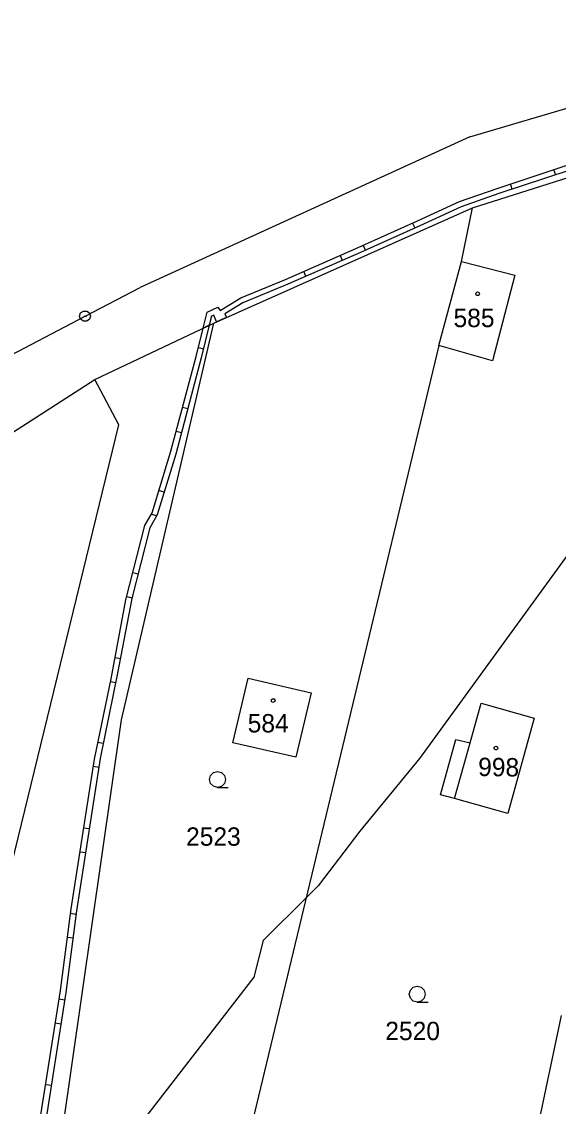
# Model space of a CAD drawing. Extents: x -760611 to -758411, y -1176479 to -1174807.
# Drawn here: x -759409.4 to -759359.7, y -1175181.7 to -1175081.4 of the extents above; entities that cross this region are included whole.
import ezdxf

# ---------------------------------------------------------------- set-up
doc = ezdxf.new("R2010")
doc.units = 0
for name, color, linetype in [('1', 7, 'Continuous'), ('11', 7, 'Continuous'), ('12', 7, 'Continuous'), ('13', 7, 'Continuous'), ('2', 7, 'Continuous'), ('3', 7, 'Continuous'), ('4', 7, 'Continuous'), ('5', 7, 'Continuous'), ('8', 7, 'Continuous')]:
    doc.layers.add(name, color=color, linetype=linetype)

msp = doc.modelspace()

# ---------------------------------------------------------------- linework, layer by layer
at = {"layer": '1'}
for p, q in [((-759367.91, -1175092.06), (-759342.24, -1175084.47)), ((-759367.67, -1175098.62), (-759342.79, -1175090.74)), ((-759367.91, -1175092.06), (-759398.41, -1175106)), ((-759391.61, -1175109.29), (-759367.67, -1175098.62)), ((-759368.7, -1175103.58), (-759367.67, -1175098.62)), ((-759370.78, -1175111.37), (-759368.7, -1175103.58)), ((-759368.7, -1175103.58), (-759363.77, -1175104.85)), ((-759363.77, -1175104.85), (-759365.83, -1175112.77)), ((-759403.51, -1175108.65), (-759398.41, -1175106)), ((-759435.58, -1175125.4), (-759403.51, -1175108.65)), ((-759402.6, -1175114.51), (-759391.61, -1175109.29)), ((-759400.15, -1175145.98), (-759391.61, -1175109.29)), ((-759370.78, -1175111.37), (-759392.87, -1175203.23)), ((-759365.83, -1175112.77), (-759370.78, -1175111.37)), ((-759421.5, -1175126.66), (-759402.6, -1175114.51)), ((-759400.38, -1175118.69), (-759402.6, -1175114.51)), ((-759410.58, -1175160.57), (-759400.38, -1175118.69)), ((-759389.84, -1175148.1), (-759388.44, -1175142.14)), ((-759388.44, -1175142.14), (-759382.61, -1175143.5)), ((-759382.61, -1175143.5), (-759384.01, -1175149.45)), ((-759367.9, -1175148.1), (-759366.88, -1175144.44)), ((-759366.88, -1175144.44), (-759361.98, -1175145.83)), ((-759408.44, -1175203.92), (-759400.15, -1175145.98)), ((-759361.98, -1175145.83), (-759364.42, -1175154.64)), ((-759384.01, -1175149.45), (-759389.84, -1175148.1)), ((-759370.64, -1175152.91), (-759369.21, -1175147.8)), ((-759369.21, -1175147.8), (-759367.9, -1175148.1)), ((-759369.34, -1175153.26), (-759370.64, -1175152.91)), ((-759364.42, -1175154.64), (-759369.34, -1175153.26)), ((-759359.46, -1175173.34), (-759362.4, -1175187.18))]:
    msp.add_line(p, q, dxfattribs=at)
at = {"layer": '11'}
msp.add_lwpolyline([(-759277.4, -1175081.41), (-759285.99, -1175083.38), (-759286.68, -1175083.54), (-759295.93, -1175086.38), (-759305.65, -1175089.38), (-759307.82, -1175090.04), (-759312.08, -1175091.35), (-759315.12, -1175092.29), (-759315.34, -1175092.43), (-759325.61, -1175098.82), (-759334.67, -1175104.46), (-759335.87, -1175105.55), (-759347.99, -1175116.51), (-759349.56, -1175117.93), (-759372.57, -1175149.55), (-759378.11, -1175156.29), (-759381.94, -1175161.35), (-759383.07, -1175162.46), (-759387.05, -1175166.4), (-759387.91, -1175169.78), (-759407.11, -1175194.59)], dxfattribs=at)
at = {"layer": '12'}
for p, q in [((-759370.78, -1175111.37), (-759368.7, -1175103.58)), ((-759368.7, -1175103.58), (-759363.77, -1175104.85)), ((-759363.77, -1175104.85), (-759365.83, -1175112.77)), ((-759365.83, -1175112.77), (-759370.78, -1175111.37)), ((-759389.84, -1175148.1), (-759388.44, -1175142.14)), ((-759388.44, -1175142.14), (-759382.61, -1175143.5)), ((-759382.61, -1175143.5), (-759384.01, -1175149.45)), ((-759367.9, -1175148.1), (-759366.88, -1175144.44)), ((-759366.88, -1175144.44), (-759361.98, -1175145.83)), ((-759361.98, -1175145.83), (-759364.42, -1175154.64)), ((-759384.01, -1175149.45), (-759389.84, -1175148.1)), ((-759369.34, -1175153.26), (-759367.9, -1175148.1)), ((-759364.42, -1175154.64), (-759369.34, -1175153.26))]:
    msp.add_line(p, q, dxfattribs=at)
at = {"layer": '13'}
for p, q in [((-759365.39, -1175096.83), (-759358.93, -1175094.68)), ((-759358.77, -1175095.16), (-759365.23, -1175097.31)), ((-759360.17, -1175095.09), (-759360.01, -1175095.57)), ((-759368.87, -1175098.04), (-759365.39, -1175096.83)), ((-759363.99, -1175096.9), (-759364.15, -1175096.42)), ((-759372.76, -1175099.82), (-759368.87, -1175098.04)), ((-759365.23, -1175097.31), (-759368.73, -1175098.52)), ((-759368.73, -1175098.52), (-759372.56, -1175100.28)), ((-759378.24, -1175102.29), (-759372.76, -1175099.82)), ((-759373.23, -1175100.03), (-759373.02, -1175100.49)), ((-759372.56, -1175100.28), (-759378.04, -1175102.75)), ((-759384.97, -1175105.24), (-759378.24, -1175102.29)), ((-759378.04, -1175102.75), (-759384.77, -1175105.7)), ((-759379.93, -1175103.03), (-759379.73, -1175103.49)), ((-759377.57, -1175102.54), (-759377.78, -1175102.08)), ((-759383.08, -1175104.96), (-759383.28, -1175104.5)), ((-759389.1, -1175106.96), (-759384.97, -1175105.24)), ((-759384.77, -1175105.7), (-759388.92, -1175107.42)), ((-759391.03, -1175108.11), (-759389.1, -1175106.96)), ((-759392.23, -1175108.28), (-759391.23, -1175107.81)), ((-759391.23, -1175107.81), (-759391.03, -1175108.11)), ((-759388.92, -1175107.42), (-759390.58, -1175108.42)), ((-759392.59, -1175109.76), (-759392.23, -1175108.28)), ((-759391.81, -1175108.64), (-759392.02, -1175109.48)), ((-759391.61, -1175108.55), (-759391.81, -1175108.64)), ((-759391.34, -1175109.17), (-759391.61, -1175108.55)), ((-759390.43, -1175108.76), (-759391.34, -1175109.17)), ((-759390.58, -1175108.42), (-759390.43, -1175108.76)), ((-759392.59, -1175109.76), (-759392.02, -1175109.48)), ((-759392.02, -1175109.48), (-759392.59, -1175109.76)), ((-759393.03, -1175111.55), (-759392.55, -1175111.67)), ((-759394.02, -1175117.23), (-759394.5, -1175117.1)), ((-759395.08, -1175119.29), (-759394.59, -1175119.42)), ((-759396.2, -1175124.92), (-759396.68, -1175124.77)), ((-759397.35, -1175126.96), (-759396.87, -1175127.1)), ((-759398.61, -1175132.51), (-759399.1, -1175132.39)), ((-759399.65, -1175134.58), (-759399.17, -1175134.7)), ((-759400.25, -1175140.34), (-759400.74, -1175140.25)), ((-759401.16, -1175142.43), (-759400.66, -1175142.53)), ((-759401.83, -1175148.18), (-759402.32, -1175148.08)), ((-759402.73, -1175150.28), (-759402.24, -1175150.35)), ((-759403.13, -1175156.07), (-759403.62, -1175156)), ((-759403.97, -1175158.18), (-759403.48, -1175158.26)), ((-759404.36, -1175163.98), (-759404.86, -1175163.91)), ((-759405.14, -1175166.09), (-759404.64, -1175166.16)), ((-759405.41, -1175171.91), (-759405.9, -1175171.83)), ((-759406.25, -1175174.01), (-759405.76, -1175174.09)), ((-759406.65, -1175179.81), (-759407.14, -1175179.73))]:
    msp.add_line(p, q, dxfattribs=at)
for points in [[(-759407.87, -1175184.28), (-759405.78, -1175171.03), (-759404.8, -1175163.47), (-759402.63, -1175149.61), (-759401.11, -1175142.19), (-759399.73, -1175134.89), (-759397.98, -1175128.02), (-759397.31, -1175126.83), (-759395.57, -1175121.14), (-759393.24, -1175112.38), (-759392.59, -1175109.76)], [(-759392.02, -1175109.48), (-759392.76, -1175112.5), (-759395.13, -1175121.42), (-759396.85, -1175127.03), (-759397.52, -1175128.22), (-759399.19, -1175134.77), (-759400.5, -1175141.68), (-759402.11, -1175149.57), (-759404.32, -1175163.65), (-759405.3, -1175171.21), (-759407.37, -1175184.4)]]:
    msp.add_lwpolyline(points, dxfattribs=at)
at = {"layer": '3'}
for points in [[(-759391.25, -1175152.23), (-759391.63, -1175152.13), (-759391.9, -1175151.86), (-759392, -1175151.49), (-759391.9, -1175151.12), (-759391.63, -1175150.85), (-759391.26, -1175150.75), (-759390.89, -1175150.85), (-759390.62, -1175151.12), (-759390.52, -1175151.5), (-759390.62, -1175151.88), (-759390.89, -1175152.15), (-759391.27, -1175152.25), (-759390.27, -1175152.25)], [(-759372.77, -1175172.09), (-759373.15, -1175171.99), (-759373.42, -1175171.72), (-759373.52, -1175171.35), (-759373.42, -1175170.98), (-759373.15, -1175170.71), (-759372.78, -1175170.61), (-759372.41, -1175170.71), (-759372.14, -1175170.98), (-759372.04, -1175171.36), (-759372.14, -1175171.74), (-759372.41, -1175172.01), (-759372.79, -1175172.11), (-759371.79, -1175172.11)]]:
    msp.add_lwpolyline(points, dxfattribs=at)
at = {"layer": '4'}
msp.add_line((-759369.34, -1175153.26), (-759367.9, -1175148.1), dxfattribs=at)
at = {"layer": '5'}
for points in [[(-759367.2, -1175106.41), (-759367.1, -1175106.43), (-759367.05, -1175106.52), (-759367.03, -1175106.58), (-759367.05, -1175106.67), (-759367.13, -1175106.74), (-759367.2, -1175106.75), (-759367.29, -1175106.72), (-759367.35, -1175106.66), (-759367.37, -1175106.58), (-759367.35, -1175106.49), (-759367.27, -1175106.42)], [(-759386.11, -1175144.03), (-759386.01, -1175144.05), (-759385.96, -1175144.14), (-759385.94, -1175144.2), (-759385.96, -1175144.29), (-759386.04, -1175144.36), (-759386.11, -1175144.37), (-759386.2, -1175144.34), (-759386.26, -1175144.28), (-759386.28, -1175144.2), (-759386.26, -1175144.11), (-759386.18, -1175144.04)], [(-759365.51, -1175148.43), (-759365.41, -1175148.45), (-759365.36, -1175148.54), (-759365.34, -1175148.6), (-759365.36, -1175148.69), (-759365.44, -1175148.76), (-759365.51, -1175148.77), (-759365.6, -1175148.74), (-759365.66, -1175148.68), (-759365.68, -1175148.6), (-759365.66, -1175148.51), (-759365.58, -1175148.44)]]:
    msp.add_lwpolyline(points, close=True, dxfattribs=at)
at = {"layer": '8'}
msp.add_line((-759403.63, -1175108.65), (-759403.39, -1175108.65), dxfattribs=at)
msp.add_lwpolyline([(-759403.36, -1175108.17), (-759403.11, -1175108.35), (-759403.01, -1175108.64), (-759403.11, -1175108.93), (-759403.36, -1175109.11), (-759403.67, -1175109.11), (-759403.92, -1175108.93), (-759404.02, -1175108.64), (-759403.92, -1175108.35), (-759403.67, -1175108.17)], close=True, dxfattribs=at)

# ---------------------------------------------------------------- texts
at = {"layer": '2'}
for s, p in [('585', (-759369.43, -1175109.66)), ('584', (-759388.47, -1175147.15)), ('2523', (-759394.17, -1175157.63)), ('2520', (-759375.74, -1175175.61))]:
    msp.add_text(s, height=1.7, dxfattribs=at).set_placement(p)
msp.add_text('998', height=1.7, rotation=359.3018, dxfattribs=at).set_placement((-759367.16, -1175151.18))

doc.saveas('drawing.dxf')
